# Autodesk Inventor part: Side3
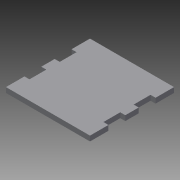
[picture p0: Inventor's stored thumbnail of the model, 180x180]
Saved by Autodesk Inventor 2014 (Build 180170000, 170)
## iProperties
Created: 2014-06
Part Number: Side3
Material: Generic
Document SubType Name: Modeling
Designer: Aser
Density: 1 g/cm^3
Appearance: Default
Author: Aser
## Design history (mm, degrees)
sketch "Sketch1"
  geometry: L1 (-25, -25)-(25, -25); L2 (25, -25)-(25, 25); L3 (25, 25)-(-25, 25); L4 (-25, 25)-(-25, -25); L5 (-25, -25)-(25, 25); L6 (25, -25)-(-25, 25); 1 further point
  constraints: 12 end point, 2 midpoint, 2 parallel, 1 horizontal, 1 perpendicular
  dimensions: "d0" = 50 distance of L3.end L2.end; "d1" = 50 distance of L2.end L1.end
extrude "Extrusion1" new body sketch "Sketch1" distance "d2" = 3; taper "d3" = 0 deg
sketch "Sketch2"
  geometry: L1 (-25, 25)-(-25, -25) reference; L2 (22, 4)-(22, 14) reference; L3 (22, 14)-(25, 14) reference; L4 (25, 4)-(25, 14) reference; L5 (22, 4)-(25, 4) reference; L6 (22, -4)-(22, -14) reference; L7 (22, -4)-(25, -4) reference; L8 (25, -14)-(25, -4) reference; L9 (22, -14)-(25, -14) reference; L10 (-25, 4)-(-25, 14) reference; L11 (-25, 14)-(-22, 14) reference; L12 (-22, 4)-(-22, 14) reference; L13 (-25, 4)-(-22, 4) reference; L14 (-25, -4)-(-25, -14) reference; L15 (-25, -4)-(-22, -4) reference; L16 (-22, -14)-(-22, -4) reference; L17 (-25, -14)-(-22, -14) reference; 1 further point
extrude "Extrusion2" cut sketch "Sketch2" distance "d4" = 3; taper "d5" = 0 deg
sketch "Sketch3"
  geometry: L1 (-25, -14)-(-25, -25) reference; L2 (-25, -25)-(25, -25) reference; L3 (25, 14)-(25, 25) reference; L4 (25, 25)-(-25, 25) reference; L5 (-25, 25)-(-25, 14) reference; L6 (-15, 25)-(-5, 25); L7 (-5, 25)-(-5, 22); L8 (-5, 22)-(-15, 22); L9 (-15, 22)-(-15, 25); L10 (15, 25)-(5, 25); L11 (5, 25)-(5, 22); L12 (5, 22)-(15, 22); L13 (15, 22)-(15, 25); L14 (-15, -25)-(-5, -25); L15 (-5, -25)-(-5, -22); L16 (-5, -22)-(-15, -22); L17 (-15, -22)-(-15, -25); L18 (5, -25)-(15, -25); L19 (15, -25)-(15, -22); L20 (15, -22)-(5, -22); L21 (5, -22)-(5, -25); 1 further point
  constraints: 32 end point, 8 parallel, 4 horizontal, 4 perpendicular, 4 point on line
  dimensions: "d6" = 10 distance of L7.end L8.end; "d7" = 3 distance of L6.end L7.end; "d8" = 10 distance of L12.end L11.end; "d9" = 3 distance of L11.end L10.end; "d10" = 10 distance between parallel lines of L5 L9; "d11" = 10 distance between parallel lines of L3 L13 (= d10); "d12" = 10 distance between parallel lines of L11 L7 (derived); "d13" = 10 distance of L16.end L15.end; "d14" = 3 distance of L15.end L14.end; "d15" = 10 distance of L20.end L19.end; "d16" = 3 distance of L19.end L18.end; "d17" = 10 distance between parallel lines of L1 L17; "d18" = 10 distance between parallel lines of L15 L21
extrude "Extrusion3" cut sketch "Sketch3" distance "d19" = 3; taper "d20" = 0 deg
sketch "Sketch4"
  geometry: L1 (-12.5, -12.5)-(12.5, -12.5); L2 (12.5, -12.5)-(12.5, 12.5); L3 (12.5, 12.5)-(-12.5, 12.5); L4 (-12.5, 12.5)-(-12.5, -12.5); L5 (-12.5, -12.5)-(12.5, 12.5); L6 (12.5, -12.5)-(-12.5, 12.5); L7 (-14, 7.5)-(-11, 7.5); L8 (-11, 7.5)-(-11, 17.5); L9 (-11, 17.5)-(-14, 17.5); L10 (-14, 17.5)-(-14, 7.5); L11 (-14, 7.5)-(-11, 17.5); L12 (-11, 7.5)-(-14, 17.5); L13 (-17.5, 11)-(-7.5, 11); L14 (-7.5, 11)-(-7.5, 14); L15 (-7.5, 14)-(-17.5, 14); L16 (-17.5, 14)-(-17.5, 11); L17 (-17.5, 11)-(-7.5, 14); L18 (-7.5, 11)-(-17.5, 14); L19 (11, 7.5)-(14, 7.5); L20 (7.5, 11)-(17.5, 11); L21 (17.5, 11)-(17.5, 14); L22 (17.5, 14)-(7.5, 14); L23 (7.5, 14)-(7.5, 11); L24 (7.5, 11)-(17.5, 14); L25 (17.5, 11)-(7.5, 14); L26 (14, 7.5)-(14, 17.5); L27 (14, 17.5)-(11, 17.5); L28 (11, 17.5)-(11, 7.5); L29 (11, 7.5)-(14, 17.5); L30 (14, 7.5)-(11, 17.5); L31 (-14, -17.5)-(-11, -17.5); L32 (-17.5, -14)-(-7.5, -14); L33 (-7.5, -14)-(-7.5, -11); L34 (-7.5, -11)-(-17.5, -11); L35 (-17.5, -11)-(-17.5, -14); L36 (-17.5, -14)-(-7.5, -11); L37 (-7.5, -14)-(-17.5, -11); L38 (-11, -17.5)-(-11, -7.5); L39 (-11, -7.5)-(-14, -7.5); L40 (-14, -7.5)-(-14, -17.5); L41 (-14, -17.5)-(-11, -7.5); L42 (-11, -17.5)-(-14, -7.5); L43 (11, -17.5)-(14, -17.5); L44 (7.5, -14)-(17.5, -14); L45 (17.5, -14)-(17.5, -11); L46 (17.5, -11)-(7.5, -11); L47 (7.5, -11)-(7.5, -14); L48 (7.5, -14)-(17.5, -11); L49 (17.5, -14)-(7.5, -11); L50 (14, -17.5)-(14, -7.5); L51 (14, -7.5)-(11, -7.5); L52 (11, -7.5)-(11, -17.5); L53 (11, -17.5)-(14, -7.5); L54 (14, -17.5)-(11, -7.5); 4 further points
  constraints: 108 end point, 18 midpoint, 6 parallel, 4 horizontal, 3 perpendicular, 1 vertical, 63 other
  dimensions: "d21" = 25 distance of L3.end L2.end; "d22" = 25 distance of L2.end L1.end; "d23" = 3 distance of L9.end L8.end; "d24" = 10 distance of L8.end L7.end; "d25" = 10 distance of L15.end L14.end; "d26" = 3 distance of L14.end L13.end; "d29" = 25 distance of L13.end L20.end; "d32" = 25 distance of L13.end L32.end
extrude "Extrusion4" cut sketch "Sketch4" distance "d35" = 3; taper "d36" = 0 deg
body "Solid1"
node "Reference1"
node "Reference2"
node "Reference3"
node "Reference4"
